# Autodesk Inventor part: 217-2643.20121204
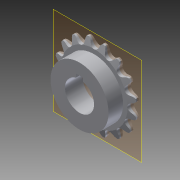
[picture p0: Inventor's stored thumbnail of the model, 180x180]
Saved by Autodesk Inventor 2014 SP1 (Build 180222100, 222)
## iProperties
Created: 2014-07
Part Number: 217-2643.20121204
Material: Aluminum 6061
Document SubType Name: Modeling
Designer: Michael
Density: 2.71 g/cm^3
Appearance: Aluminum - Flat
Author: svradm
Title: 217-2643-001.20121204.STEP
Organization: Microsoft
Description: STEP AP203
Creation Date: 2012-12-04
Sending System: SolidWorks 2012
Preprocessor: SwSTEP 2.0
Author: Michael
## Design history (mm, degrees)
node "217-2643.201212041"
workplane "Work Plane1"
node "Cut-Extrude2"
node "Base1"
